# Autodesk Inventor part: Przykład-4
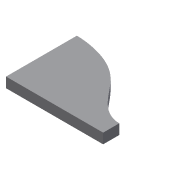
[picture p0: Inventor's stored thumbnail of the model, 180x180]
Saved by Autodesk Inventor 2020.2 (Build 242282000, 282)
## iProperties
Created: 2006-03
Part Number: Przykład-4
Document SubType Name: Modeling
Designer: F.Stasiak
Density: 1 g/cm^3
Material: Ogólny
Appearance: Domyślna
Manager: www.cadconsulting.pl
Company: Fabian Stasiak CAD Consulting
Author: F.Stasiak
Subject: Zbiór ćwiczeń. Autodesk Inventor 2020. Kurs podstawowy
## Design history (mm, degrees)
sketch "Szkic1"
  geometry: L1 (0, 0)-(0, 35); L2 (0, 0)-(48, 0); L3 (48, 0)-(48, 8); L4 (-6.707, 35)-(6.707, 35); L5 (39.509, 8)-(56.491, 8); A1 r 26.253 centre (0, 8.747) between (6.498, 34.183) and (-6.498, 34.183); 5 further points
  constraints: 10 end point, 4 midpoint, 4 perpendicular, 2 horizontal, 1 centre point, 1 point on circle, 1 vertical, 9 other
  dimensions: "d0" = 48 distance of L1.start L2.end; "d1" = 35 distance of L1.start L1.end; "d2" = 8 distance of L2.end L3.end
extrude "Wyciągnięcie proste1" new body sketch "Szkic1" distance "d3" = 5; taper "d4" = 0 deg
node "Bryła1"
node "Korpusy bryłowe"
node "Korpusy powierzchniowe"
